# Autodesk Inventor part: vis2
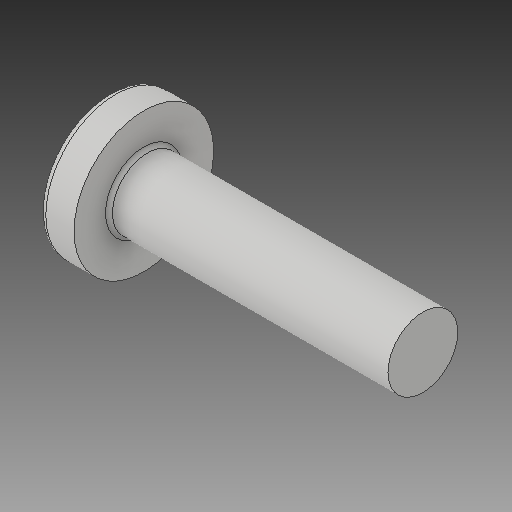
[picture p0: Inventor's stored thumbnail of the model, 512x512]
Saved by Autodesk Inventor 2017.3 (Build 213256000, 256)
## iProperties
Created: 1999-08
Part Number: vis2
Material: Générique
Document SubType Name: Modeling
Designer: ficho
Density: 1 g/cm^3
Appearance: Par défaut
Author: ficho
Sending System: SolidWorks 2009
Last Author: tof
Last Saved: 2010-07-07
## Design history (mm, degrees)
feature "RecessCore"
node "Solide1"
